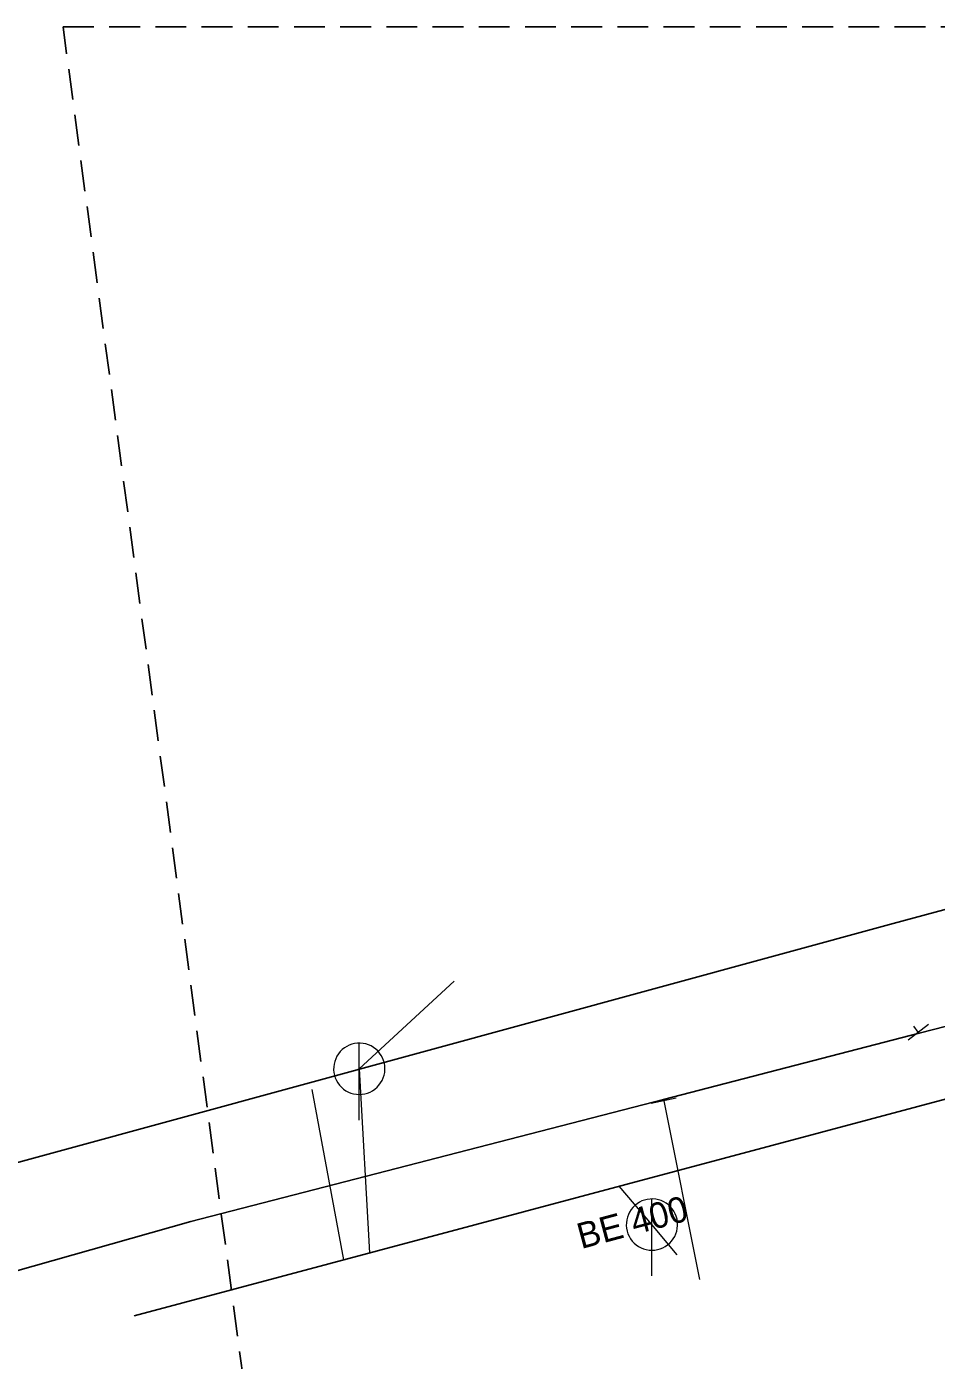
# Model space of a CAD drawing. Extents: x -682839 to -682312, y -994645 to -993949.
# Drawn here: x -682752.8 to -682717.4, y -994094.5 to -994042.5 of the extents above; entities that cross this region are included whole.
import ezdxf

# ---------------------------------------------------------------- set-up
doc = ezdxf.new("R2010")
doc.units = 0
doc.header["$LTSCALE"] = 0.4
doc.linetypes.add('MEDIUM_DASHED', pattern=[4.5, 3, -1.5])
doc.layers.add('1', color=7, linetype='Continuous')
for name, color, linetype, lineweight in [('11', 7, 'Continuous', 13), ('13', 7, 'Continuous', 13), ('14', 7, 'Continuous', 25), ('17', 7, 'Continuous', 25), ('22', 7, 'Continuous', 13), ('34', 7, 'Continuous', 13), ('63', 7, 'MEDIUM_DASHED', 25)]:
    doc.layers.add(name, color=color, linetype=linetype, lineweight=lineweight)

msp = doc.modelspace()

# ---------------------------------------------------------------- linework, layer by layer
at = {"layer": '11'}
for p, q in [((-682736.179, -994079.706), (-682739.87, -994083.12)), ((-682739.87, -994083.12), (-682739.467, -994090.291)), ((-682741.719, -994083.93), (-682740.48, -994090.559)), ((-682728.468, -994089.19), (-682729.751, -994087.698)), ((-682727.48, -994090.363), (-682728.468, -994089.19))]:
    msp.add_line(p, q, dxfattribs=at)
at = {"layer": '13'}
for p, q in [((-682718.091, -994081.688), (-682718.27, -994081.46)), ((-682728.01, -994084.368), (-682726.609, -994091.329))]:
    msp.add_line(p, q, dxfattribs=at)
at = {"layer": '14', "lineweight": 13}
for p, q in [((-682718.061, -994081.728), (-682718.091, -994081.688)), ((-682728.02, -994084.32), (-682728.01, -994084.368))]:
    msp.add_line(p, q, dxfattribs=at)
at = {"layer": '14'}
msp.add_line((-682709.039, -994082.17), (-682748.64, -994092.739), dxfattribs=at)
at = {"layer": '17'}
for points in [[(-682473.55, -994045.57), (-682522.289, -994043.899), (-682529.616, -994044.905), (-682556.26, -994048.129), (-682661.506, -994061.932), (-682719.074, -994077.464), (-682816.699, -994104.109)], [(-682788.97, -994100.714), (-682780.37, -994098.68), (-682746.43, -994089.07), (-682728.02, -994084.32), (-682718.061, -994081.728), (-682709.855, -994079.629)]]:
    msp.add_lwpolyline(points, dxfattribs=at)
at = {"layer": '22'}
for p, q in [((-682739.87, -994085.12), (-682739.869, -994082.12)), ((-682728.468, -994091.19), (-682728.467, -994088.19))]:
    msp.add_line(p, q, dxfattribs=at)
for points in [[(-682738.87, -994083.12), (-682738.875, -994083.011), (-682738.893, -994082.903), (-682738.923, -994082.797), (-682738.963, -994082.696), (-682739.015, -994082.599), (-682739.077, -994082.509), (-682739.149, -994082.426), (-682739.229, -994082.352), (-682739.317, -994082.286), (-682739.411, -994082.231), (-682739.511, -994082.186), (-682739.616, -994082.153), (-682739.723, -994082.131), (-682739.832, -994082.121), (-682739.942, -994082.123), (-682740.05, -994082.137), (-682740.157, -994082.162), (-682740.26, -994082.199), (-682740.358, -994082.248), (-682740.45, -994082.306), (-682740.536, -994082.375), (-682740.613, -994082.452), (-682740.682, -994082.538), (-682740.741, -994082.63), (-682740.789, -994082.728), (-682740.826, -994082.831), (-682740.852, -994082.938), (-682740.866, -994083.046), (-682740.869, -994083.156), (-682740.859, -994083.265), (-682740.838, -994083.372), (-682740.804, -994083.476), (-682740.76, -994083.576), (-682740.705, -994083.671), (-682740.639, -994083.759), (-682740.565, -994083.839), (-682740.482, -994083.911), (-682740.392, -994083.973), (-682740.296, -994084.025), (-682740.194, -994084.066), (-682740.089, -994084.096), (-682739.981, -994084.114), (-682739.871, -994084.12), (-682739.762, -994084.114), (-682739.654, -994084.096), (-682739.549, -994084.067), (-682739.447, -994084.026), (-682739.35, -994083.974), (-682739.26, -994083.912), (-682739.177, -994083.841), (-682739.102, -994083.761), (-682739.037, -994083.673), (-682738.981, -994083.579), (-682738.937, -994083.479), (-682738.903, -994083.375), (-682738.881, -994083.267), (-682738.871, -994083.158)], [(-682727.468, -994089.19), (-682727.473, -994089.081), (-682727.491, -994088.973), (-682727.521, -994088.867), (-682727.561, -994088.766), (-682727.613, -994088.669), (-682727.675, -994088.579), (-682727.747, -994088.496), (-682727.827, -994088.422), (-682727.915, -994088.356), (-682728.009, -994088.301), (-682728.109, -994088.256), (-682728.214, -994088.223), (-682728.321, -994088.201), (-682728.43, -994088.191), (-682728.54, -994088.193), (-682728.648, -994088.207), (-682728.755, -994088.232), (-682728.858, -994088.269), (-682728.956, -994088.318), (-682729.048, -994088.376), (-682729.134, -994088.445), (-682729.211, -994088.522), (-682729.28, -994088.608), (-682729.339, -994088.7), (-682729.387, -994088.798), (-682729.424, -994088.901), (-682729.45, -994089.008), (-682729.464, -994089.116), (-682729.467, -994089.226), (-682729.457, -994089.335), (-682729.436, -994089.442), (-682729.402, -994089.546), (-682729.358, -994089.646), (-682729.303, -994089.741), (-682729.237, -994089.829), (-682729.163, -994089.909), (-682729.08, -994089.981), (-682728.99, -994090.043), (-682728.894, -994090.095), (-682728.792, -994090.136), (-682728.687, -994090.166), (-682728.579, -994090.184), (-682728.469, -994090.19), (-682728.36, -994090.184), (-682728.252, -994090.166), (-682728.147, -994090.137), (-682728.045, -994090.096), (-682727.948, -994090.044), (-682727.858, -994089.982), (-682727.775, -994089.911), (-682727.7, -994089.831), (-682727.635, -994089.743), (-682727.579, -994089.649), (-682727.535, -994089.549), (-682727.501, -994089.445), (-682727.479, -994089.337), (-682727.469, -994089.228)]]:
    msp.add_lwpolyline(points, close=True, dxfattribs=at)
at = {"layer": '34'}
for p, q in [((-682718.487, -994081.992), (-682717.693, -994081.384)), ((-682727.52, -994084.268), (-682728.5, -994084.466))]:
    msp.add_line(p, q, dxfattribs=at)
at = {"layer": '63'}
msp.add_lwpolyline([(-682494.62, -994477.955), (-682564.4, -994570.065), (-682564.4, -994570.065), (-682684.423, -994544.944), (-682684.423, -994544.944), (-682751.412, -994042.525), (-682751.412, -994042.525), (-682670.466, -994042.525), (-682670.466, -994042.525)], close=True, dxfattribs=at)

# ---------------------------------------------------------------- texts
at = {"layer": '1'}
msp.add_text('BE 400', height=1, rotation=15, dxfattribs=at).set_placement((-682731.225, -994090.146))

doc.saveas('drawing.dxf')
